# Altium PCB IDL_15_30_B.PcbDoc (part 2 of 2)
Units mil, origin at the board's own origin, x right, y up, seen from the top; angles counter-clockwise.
Board outline 4133.86 x 2440.94 mil, 4 copper layers (Top Layer - SIG1, Layer 2 - GND1, Layer 3 - SIG2, Bottom Layer - SIG4), stack 63.086 mil thick; 140 components, 50 nets, 376 pads, 452 vias.
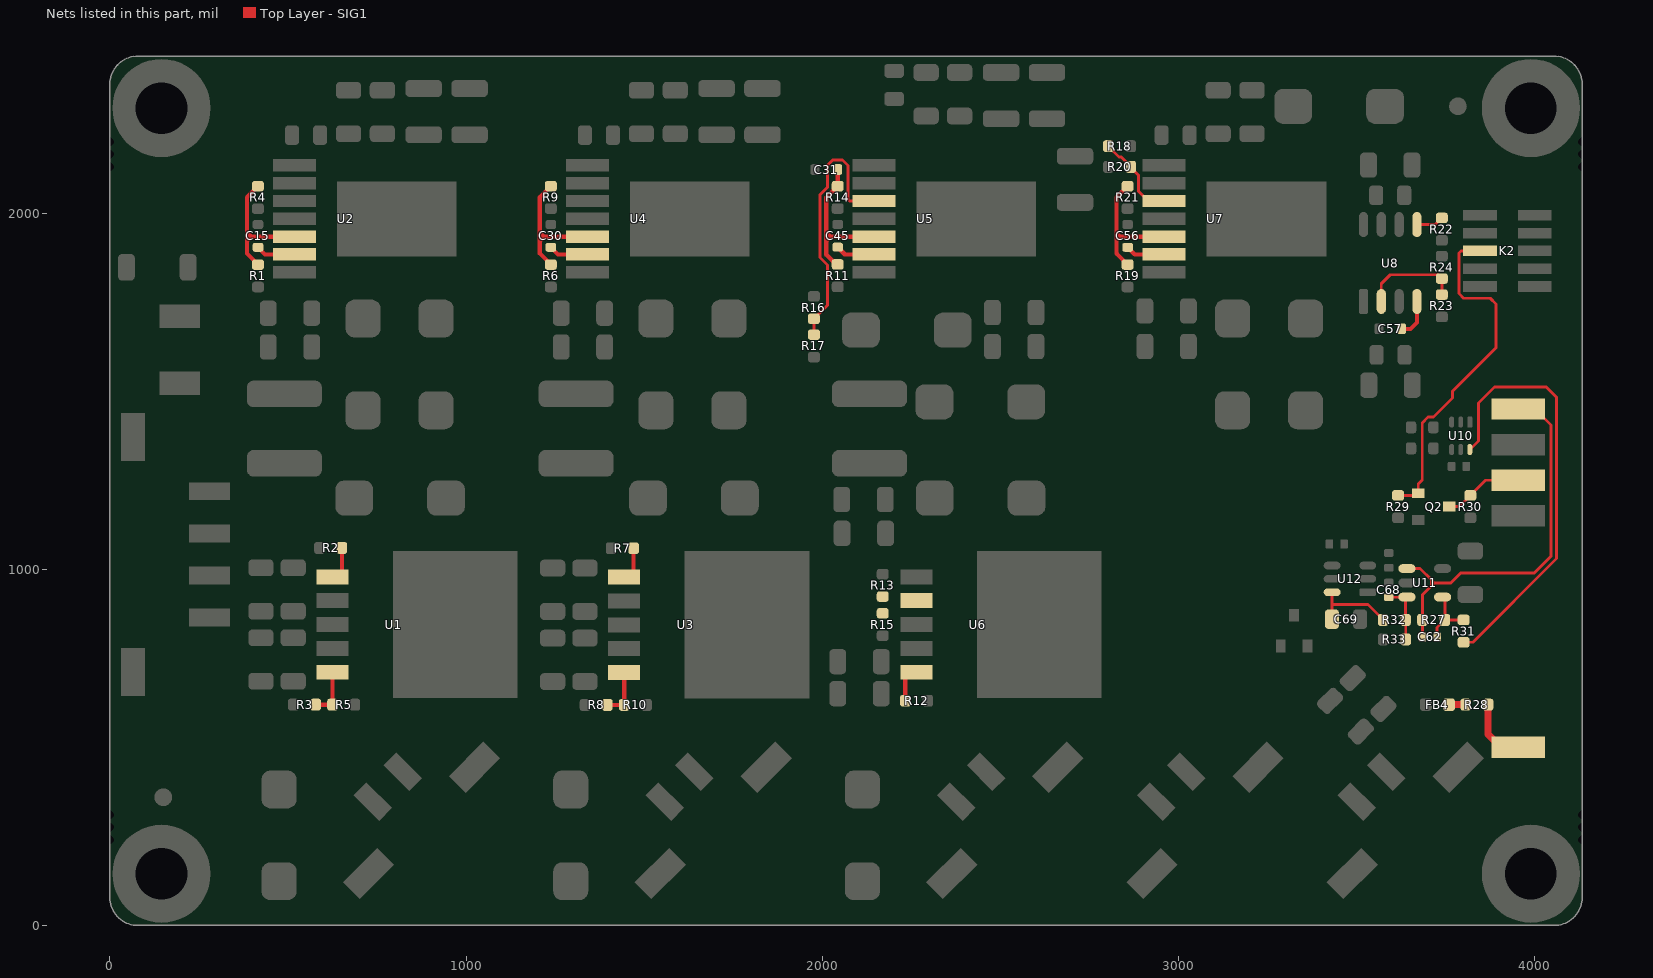
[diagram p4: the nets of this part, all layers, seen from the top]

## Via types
v1: diameter 25.59, hole 11.81, Top Layer - SIG1 to Bottom Layer - SIG4, tented both sides, 262 vias
v2: diameter 31.5, hole 15.75, Top Layer - SIG1 to Bottom Layer - SIG4, tented both sides, 154 vias
v3: diameter 31.5, hole 15.75, Top Layer - SIG1 to Bottom Layer - SIG4, tented top, 36 vias

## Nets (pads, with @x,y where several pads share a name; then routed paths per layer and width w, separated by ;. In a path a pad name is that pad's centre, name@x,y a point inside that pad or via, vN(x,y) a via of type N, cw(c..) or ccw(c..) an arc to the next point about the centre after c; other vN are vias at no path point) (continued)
HVEN#: K2.6 Q2.1 R29.1 | length 981.9
  Top Layer - SIG1 w8: R29.1@3617,1207.5 3667.79,1207.5 Q2.1@3673.69,1213.4 3673.69,1239.69 3684.87,1250.87 3684.87,1411.21 3700.96,1427.29 3716.3,1427.29 3770,1480.99 3770,1499.88 3892,1621.88 3892,1745 3876,1761 3801.05,1761 3787.98,1774.07 3787.98,1887.98 3794,1894 K2.6@3847.23,1894
NetC15_2: C15.2 U2.6 | length 110.7
  Top Layer - SIG1 w12: C15.2@415.87,1904.13 435.87,1884.13 U2.6@518.27,1884.13
NetC30_2: C30.2 U4.6 | length 221.4
  Top Layer - SIG1 w12: 1258.23,1884.13 C30.2@1238.23,1904.13 1258.23,1884.13 ; 1258.23,1884.13 U4.6@1340.63,1884.13 1258.23,1884.13
NetC31_1: C31.1 R11.1 R14.2 U5.5 | length 453.4
  Top Layer - SIG1 w12: 2011.73,1922.27 2023.6,1934.13 ; 2011.73,1946 2023.6,1934.13 ; R11.1@2042.6,1856.99 R11.1@2043.6,1855.99 ; C31.1@2043.6,2122.5 R14.2@2043.6,2075.99 2011.73,2044.13 2011.73,1883.27 2036.57,1858.43 R11.1@2046.03,1858.43 ; U5.5@2145,1934.13 2023.6,1934.13
NetC45_2: C45.2 U5.6 | length 110.7
  Top Layer - SIG1 w12: C45.2@2043.6,1904.5 2063.6,1884.5 ; 2062.6,1884.13 U5.6@2145,1884.13
NetC56_2: C56.2 U7.6 | length 110.7
  Top Layer - SIG1 w12: C56.2@2857.6,1904.13 2877.6,1884.13 U7.6@2960,1884.13
NetC57_1: C57.1 U8.4 | length 109.5
  Top Layer - SIG1 w12: C57.1@3627,1675 3652,1675 3670,1693 U8.4@3670,1752
NetC62_1: C62.1 R27.1 R31.1 U11.4 | length 176.2
  Top Layer - SIG1 w8: C62.1@3726.67,810 3726.67,836.17 R27.1@3748.5,858 ; U11.4@3742,922 3748.5,915.5 R27.1@3748.5,858 ; R31.1@3801,858 R27.1@3748.5,858
NetC62_2: C62.2 pad.1 R27.2 U11.1 | length 1121.2
  Top Layer - SIG1 w8: U11.1@3642,1002 3679,1002 3710,971 ; C62.2@3685.33,810 R27.2@3685.33,857.83 ; R27.2@3685.5,858 3685.5,928.5 3710,953 ; pad.1@3955,1450 pad.1@4001,1450 ; pad.1@4009,1450 pad.1@4001,1450 ; 3710,953 3719,962 ; 3710,953 3710,971 ; 3710,971 3719,962 ; 3719,962 3765,962 3793,990 3999.37,990 4046,1036.63 4046,1405 pad.1@4001,1450
NetC68_2: C68.2 R32.1 R33.2 U11.3 | length 171.2
  Top Layer - SIG1 w8: C68.2@3591,921.33 U11.3@3641.33,921.33 ; R33.2@3638.5,803 3638.5,857.5 R32.1@3638,858 3638,918 U11.3@3641.33,921.33 ; U11.3@3642,922 U11.3@3641.33,921.33
NetC69_2: C69.2 R32.2 U12.6 | length 246.4
  Top Layer - SIG1 w8: C69.2@3431.87,852.13 U12.6@3431.87,935.73 ; 3432,901 3533,901 3576,858 R32.2@3575.01,858
NetFB4_1: FB4.1 R28.2 | length 47
  Top Layer - SIG1 w20: FB4.1@3760,620 R28.2@3807.01,620
NetQ2_3: pad.3 Q2.3 R30.1 | length 233.3
  Top Layer - SIG1 w8: Q2.3@3760.31,1176 3788.5,1176 R30.1@3820,1207.5 3838.5,1226 3862.5,1250 pad.3@3963,1250
NetR1_1: R1.1 R4.2 U2.5 | length 400.5
  Top Layer - SIG1 w12: R1.1@415.87,1855.63 385,1886.5 385,1922.27 ; R4.2@415.87,2075.63 387.13,2046.9 385,2044.76 385,1946 ; U2.5@518.27,1934.13 396.87,1934.13 ; 385,1922.27 385,1946 ; 385,1922.27 396.87,1934.13 ; 385,1946 396.87,1934.13
NetR2_1: R2.1 U1.1 | length 100.2
  Top Layer - SIG1 w12: U1.1@625,979 639,979 651.5,991.5 R2.1@651.5,1060
NetR3_1: R3.1 R5.2 U1.5 | length 138
  Top Layer - SIG1 w12: R3.1@577.99,620 R5.2@625,620 U1.5@625,711
NetR6_1: R6.1 R9.2 U4.5 | length 400.5
  Top Layer - SIG1 w12: R6.1@1238.23,1855.63 1207.36,1886.5 1207.36,1922.27 ; R9.2@1238.23,2075.63 1209.5,2046.9 1207.36,2044.76 1207.36,1946 ; U4.5@1340.63,1934.13 1219.23,1934.13 ; 1207.36,1922.27 1219.23,1934.13 ; 1207.36,1922.27 1207.36,1946 ; 1207.36,1946 1219.23,1934.13
NetR7_1: R7.1 U3.1 | length 100.2
  Top Layer - SIG1 w12: U3.1@1444.05,978.13 1458.05,978.13 1470.55,990.63 R7.1@1470.55,1059.13
NetR8_1: R8.1 R10.2 U3.5 | length 138
  Top Layer - SIG1 w12: R8.1@1397.05,619.13 R10.2@1444.05,619.13 U3.5@1444.05,710.13
NetR12_1: R12.1 U6.5 | length 80
  Top Layer - SIG1 w12: R12.1@2233.5,631 U6.5@2233.5,711
NetR13_1: R13.1 R15.2 U6.2
NetR16_2: R16.2 R17.1 U5.3 | length 749
  Top Layer - SIG1 w8: R17.1@1977,1659 R16.2@1977,1703.5 2014.87,1741.37 2014.87,1854.68 1993.73,1875.81 1993.73,2051.58 2014.87,2072.72 2014.87,2134.57 2029.79,2149.5 2057.41,2149.5 2072.76,2134.14 2072.76,2038.24 2076.87,2034.13 U5.3@2145,2034.13
NetR18_1: R18.1 R20.1 U7.3 | length 249
  Top Layer - SIG1 w8: R18.1@2803.5,2188 2803.5,2187.5 2833,2158 2840,2158 2866.5,2131.5 R20.1@2866.5,2130 2866.5,2127.64 2887.76,2106.37 2887.76,2061.64 2915.27,2034.13 U7.3@2960,2034.13
NetR19_1: R19.1 R21.2 U7.5 | length 396.9
  Top Layer - SIG1 w12: 2826.73,1924.27 2836.6,1934.13 ; 2826.73,1944 2836.6,1934.13 ; R19.1@2857.6,1855.63 2828.87,1884.36 2826.73,1886.5 2826.73,2044.76 R21.2@2857.6,2075.63 ; U7.5@2960,1934.13 2836.6,1934.13
NetR22_1: R22.1 U8.5 | length 77.7
  Top Layer - SIG1 w8: U8.5@3670,1968 3721.5,1968 R22.1@3740,1986.5
NetR23_1: R23.1 R24.2 U8.2 | length 279.6
  Top Layer - SIG1 w8: U8.2@3570,1752 3570,1802 3595,1827 3729.38,1827 R24.2@3740,1816.38 R23.1@3740,1771.5
NetR28_1: pad.5 R28.1 | length 208.9
  Top Layer - SIG1 w20: R28.1@3870,620 3870,536 3906,500 pad.5@3980,500
NetR31_2: R31.2 U10.6 | length 1201.9
  Top Layer - SIG1 w8: R31.2@3801,795.01 3827.01,795.01 4062,1030 4062,1483 4033,1512 3888,1512 3843,1467 3843,1360.64 U10.6@3818.59,1336.23
pads on no net: FID1.0 FID2.0 K1.MP1 K1.MP2 K4.MP1 K4.MP2 K5.MP1 K5.MP2 K6.MP1 K6.MP2 K7.MP1 K7.MP2 K8.MP1 K8.MP2 ME1.0 ME1.1 ME1.2 ME2.0 ME2.1 ME2.2 ME3.0 ME3.1 ME3.2 ME4.0 ME4.1 ME4.2

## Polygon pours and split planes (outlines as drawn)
+12VIN_3 on Top Layer - SIG1 "L1_+12V" (solid, remove dead copper, pour order 0): 20,1580 355,1580 355,2057 376,2078 376,2095 391,2110 616,2110 616,2134 570,2180 570,2242 576,2248 1052,2248 1062,2238 1062,2130 1085,2107 1438,2107 1438.36,2107.36 1438.36,2134 1392.36,2180 1392.36,2242 1398.36,2248 1874.36,2248 1884.36,2238 1884.36,2173.64 1905,2153 2053.9,2153 2072.76,2134.14 2072.76,2110 2757.76,2110 2769,2121.24 2769,2160 2769,2200 2777,2208 2816,2208 2821,2203 2821,2170 2833,2158 2840,2158 2866.5,2131.5 2887.76,2110.24 2887.76,2106.37 3057.37,2106.37 3058,2107 3057.73,2134 3011.73,2180 3011.73,2242 3017.73,2248 3237.16,2248 3407.39,2077.77 3458,2077.77 3458,1932 3470,1920 3531,1920 3543,1932 3543,1998 3555,2010 3577,2010 3589,2022 3589,2139 3522,2206 3307,2421 3191,2421 295,2421 295,2232 208,2145 20,2145
GND on Top Layer - SIG1 "L1_GND" (solid, remove dead copper, pour order 4): 20,2157 20,2363 cw(c78,2363) 78,2421 4054,2421 cw(c4054,2361) 4114,2361 4114,80 cw(c4054,80) 4054,20 75.15,20 cw(c75.15,75.15) 20,75.15
GND on Layer 3 - SIG2 "L3_GND" (solid, remove dead copper, pour order 6): 20,2157 20,2363 cw(c78,2363) 78,2421 4054,2421 cw(c4054,2361) 4114,2361 4114,80 cw(c4054,80) 4054,20 75.15,20 cw(c75.15,75.15) 20,75.15
GND on Bottom Layer - SIG4 "L4_GND" (solid, remove dead copper, pour order 8): 20,2157 20,2363 cw(c78,2363) 78,2421 4054,2421 cw(c4054,2361) 4114,2361 4114,80 cw(c4054,80) 4054,20 75.15,20 cw(c75.15,75.15) 20,75.15
GND on Layer 2 - GND1 (split plane): 4061.69,2420.57 4068.19,2419.46 4074.52,2417.64 4080.6,2415.12 4086.37,2411.94 4091.74,2408.12 4096.65,2403.73 4101.04,2398.82 4104.85,2393.45 4108.03,2387.69 4110.55,2381.6 4112.38,2375.27 4113.48,2368.78 4113.82,2362.78 4113.76,2362.2 4113.76,78.74 4113.82,78.16 4113.48,72.16 4112.38,65.67 4110.55,59.34 4108.03,53.26 4104.85,47.49 4101.04,42.12 4096.65,37.21 4091.74,32.82 4086.37,29.01 4080.6,25.82 4074.52,23.3 4068.19,21.48 4061.69,20.38 4055.69,20.04 4055.12,20.1 78.74,20.1 78.16,20.04 72.16,20.38 65.67,21.48 59.34,23.3 53.26,25.82 47.49,29.01 42.12,32.82 37.21,37.21 32.82,42.12 29.01,47.49 25.82,53.26 23.3,59.34 21.48,65.67 20.38,72.16 20.04,78.16 20.1,78.74 20.1,2362.2 20.04,2362.78 20.38,2368.78 21.48,2375.27 23.3,2381.6 25.82,2387.69 29.01,2393.45 32.82,2398.82 37.21,2403.73 42.12,2408.12 47.49,2411.94 53.26,2415.12 59.34,2417.64 65.67,2419.46 72.16,2420.57 78.16,2420.9 78.74,2420.85 4055.12,2420.85 4055.69,2420.9

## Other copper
Top Layer - SIG1:
  pour cut-out: 2200,1858.61 2252.68,1858.61 2252.68,1957.84 2200,1957.84
  pour cut-out: 1178.65,1297.65 1189.9,1297.65 1189.9,1289 1182.24,1289
  pour cut-out: 1192.29,297.37 1182.24,297.37 1182.24,303.13 1198.05,303.13
  region net +5VA_SW1_3: 1278.36,1858 1406.36,1858 1413.36,1851 1413.36,1804 1402.36,1793 1360.36,1793 1332.36,1765 1332.36,1588 1358.36,1562 1884.36,1562 1884.36,1418 1842.36,1376 1238.36,1376 1201.36,1413 1201.36,1803 1214.36,1816 1245.36,1816 1264.39,1835.03 1264.39,1844.03
  region net +3VA_SW2_3: 379,1328 379,939 394,924 538,924 574,888 672,888 672,945 577,945 568,954 568,1006 577,1015 610,1015 622,1027 622,1075 637,1090 741,1090 760,1109 760,1331 741,1350 401,1350
  region net +3VA_SW1_3: 456,1858 584,1858 591,1851 591,1804 580,1793 538,1793 510,1765 510,1588 536,1562 1062,1562 1062,1418 1020,1376 416,1376 379,1413 379,1803 392,1816 423,1816 442.03,1835.03 442.03,1844.03
  region net GND: 1221.36,2023 1227.36,2029 1251.36,2029 1277.36,2003 1498.11,2003 1498.11,1966 1262.36,1966 1250.36,1954 1227.36,1954 1221.36,1960
  region net GND: 399,2023 405,2029 429,2029 455,2003 675.75,2003 675.75,1966 440,1966 428,1954 405,1954 399,1960
  region net GND: 1392.36,2242 1398.36,2248 1874.36,2248 1884.36,2238 1884.36,1586 1368.36,1586 1356.36,1598 1356.36,1755 1370.36,1769 1412.36,1769 1438.36,1795 1438.36,2134 1392.36,2180
  region net GND: 570,2242 576,2248 1052,2248 1062,2238 1062,1586 546,1586 534,1598 534,1755 548,1769 590,1769 616,1795 616,2134 570,2180
  region net GND: 20,1046.85 335,1046.85 350,1031.85 350,806.85 335,791.85 20,791.85
  region net +12VIN*_3: 335,1056.85 353,1074.85 353,1566.85 348,1571.85 20,1571.85 20,1451.85 100,1451.85 110,1441.85 110,1071.85 125,1056.85
  region net GND: 3453,1040 3453,1082 3458,1087 3499,1087 3565,1021 3602,1021 3609,1014 3609,988 3618,979 3663,979 3669,973 3669,951 3663,945 3575,945 3554,924 3499,924 3483,940 3483,1010
  region net GND: 3795,885 3875,885 3895,905 3895,945 3875,965 3795,965 3780,950 3780,900
  region net GND: 3464,881 3472,889 3527,889 3545,871 3545,846 3561,830 3586,830 3594,822 3594,774 3587,767 3557,767 3496,828 3472,828 3464,836
  region net GND: 2145,2421 2715,2421 2715,2380 2705,2370 2154,2370 2145,2379
  region net GND: 378.9,892.9 394,908 541,908 580,869 970,869 970,820 580,820 541,781 393.9,781 378.9,796
  region net +2V5_3: 379,743 407,771 543,771 582,810 672,810 672,751 587,751 564,728 564,649 554,639 554,599 813,340 813,314 750,251 432,251 379,304
  region net GND: 1197.95,892.03 1213.05,907.13 1360.05,907.13 1399.05,868.13 1789.05,868.13 1789.05,819.13 1399.05,819.13 1360.05,780.13 1212.95,780.13 1197.95,795.13
  region net +4V5A_3: 1198.05,742.13 1226.05,770.13 1362.05,770.13 1401.05,809.13 1491.05,809.13 1491.05,750.13 1406.05,750.13 1383.05,727.13 1383.05,648.13 1373.05,638.13 1373.05,598.13 1632.05,339.13 1632.05,313.13 1569.05,250.13 1251.05,250.13 1198.05,303.13
  region net -5.4VA_SW1_3: 2025.73,2023 2031.73,2029 2055.73,2029 2081.73,2003 2432.6,2003 2432.6,1966 2066.73,1966 2054.73,1954 2031.73,1954 2025.73,1960
  region net +5VA_SW2_3: 1198.05,1328 1198.05,939 1213.05,924 1357.05,924 1393.05,888 1491.05,888 1491.05,945 1396.05,945 1387.05,954 1387.05,1006 1396.05,1015 1429.05,1015 1441.05,1027 1441.05,1075 1456.05,1090 1560.05,1090 1579.05,1109 1579.05,1331 1560.05,1350 1220.05,1350
  region net -5.4VA_SW1_3: 2252,2097.04 2265.08,2110.12 2757.88,2110.12 2769,2099 2769,2004 2530,1765 2530,1597 2353,1420 2049.77,1420 2016.77,1453 2016.77,1493 1960,1549.77 1960,1608 1965,1613 1998,1613 2042,1569 2176,1569 2252,1645
  region net GND: 2027,1809 2036,1818 2057,1818 2068,1829 2068,1843 2080,1855 2234,1855 2243,1846 2243,1650 2172,1579 2046,1579 2008,1617 2008,1717 2027,1736
  region net -5.4VA_SW2_3: 2016,1322 2045,1351 2270,1351 2582,1039 2582,638 2431,638 2331,738 2331,997 2318,1010 2151,1010 2115,1046 2115,1231 2100,1246 2026,1246 2016,1256
  region net NetR13_1: 2154,861 2150,865 2150,932 2159,941 2315,941 2315,887 2212,887 2186,861
  region net -4V5A_3: 2103,772 2103,814 2120.09,831.09 2198.09,831.09 2220.05,809.13 2310.05,809.13 2310.05,750.13 2225.05,750.13 2209,734.08 2209,581.19 2451.05,339.13 2451.05,313.13 2388.05,250.13 2070.05,250.13 2017.05,303.13 2017.06,423.13 2017.06,526.06 2103,612
  region net GND: 3011.73,2242 3017.73,2248 3237.16,2248 3458,2077.77 3458,1586 2987.73,1586 2975.73,1598 2975.73,1755 2989.73,1769 3031.73,1769 3057.73,1795 3057.73,2134 3011.73,2180
  region net +3V3D_3: 2897.73,1858 3025.73,1858 3032.73,1851 3032.73,1804 3021.73,1793 2979.73,1793 2951.73,1765 2951.73,1588 2977.73,1562 3458,1562 3458,1395.27 3438.73,1376 3007,1376 2977.73,1346.73 2977.73,518 2937.86,478.14 2937.86,458 2988.43,407.43 3040.43,355.43 3040.43,305 3015.22,279.78 2867.95,279.78 2820.73,327 2820.73,518 2820.73,1413 2820.73,1803 2833.73,1816 2864.73,1816 2883.76,1835.03 2883.76,1844.03
  region net +5HV: 3700,1121 3700,1280 3740,1320 3740,1347 3746,1353 3774,1353 3778,1349 3778,1238 3734,1194 3734,1159 3742,1151 3786,1151 3819,1184 4032,1184 4032,1045 3992,1005 3790,1005 3760,975 3730,975 3676,1029 3569,1029 3503,1095 3454,1095 3445,1086 3445,1036 3464,1017 3464,1001 3457,994 3411,994 3403,1002 3403,1327 3468,1392 3468,1793 3536,1793 3543,1786 3543,1724 3591,1676 3591,1500 3671,1420 3671,1376 3662,1367 3641,1367 3630,1356 3630,1260 3592,1222 3592,1175 3600,1167 3634,1167 3642,1159 3642,1124 3651,1115 3694,1115
  region net GND: 20,1901.85 83,1901.85 99,1885.85 99,1809.85 83,1793.85 20,1793.85
  region net GND: 2840.73,2023 2846.73,2029 2870.73,2029 2896.73,2003 3117.48,2003 3117.48,1966 2881.73,1966 2869.73,1954 2846.73,1954 2840.73,1960
  pour cut-out: 1072.2,2119.8 1072.2,1562 536,1562 510,1588 510,1765 538,1793 580,1793 580,1916 561,1935 396,1935 385,1946 385,2044.76 451,2102 755,2102 1057.87,2134.13
  pour cut-out: 1894.56,2163.44 1894.56,1562 1358.36,1562 1332.36,1588 1332.36,1765 1360.36,1793 1402.36,1793 1402.36,1916 1383.36,1935 1218.36,1935 1207.36,1946 1207.36,2044.76 1273.36,2102 1577.36,2102 1873,2163.44
  pour cut-out: 3468.2,1921.8 3468.2,1562 2977.73,1562 2951.73,1588 2951.73,1765 2979.73,1793 3021.73,1793 3021.73,1916 3002.73,1935 2837.73,1935 2826.73,1946 2826.73,2044.76 2892.73,2102 3196.73,2102
  pour cut-out: 371.46,935.88 370.84,939 370.84,740 394,740 407,771 407,911 394,924
  pour cut-out: 1154.05,848.94 1187.86,815.13 1187.86,739.13 1213.05,739.13 1226.05,770.13 1226.05,910.13 1213.05,923.13
  pour cut-out: 379,304 379,11 368.8,11 368.8,309.45

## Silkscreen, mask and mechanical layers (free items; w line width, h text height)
Top Overlay:
  lines w3.94: 3500,1350 3500,1110 3570,1050 3570,920
  text "+12V" at 215,2025 h120 r45
  text "UHM-HEP Group" at 2931.94,551.35 h59.06 r90
  text "ID Laboratory" at 3016.94,551.35 h59.06 r90
  text "IDL_15_30 Rev.B" at 3101.94,551.35 h47.24 r90
  text "HV" at 3739.43,107.43 h120 r45
  text "+2V5" at 935,65 h120 r45
  text "+4V5A" at 1754,65 h120 r45
  text "-4V5A" at 2573,65 h120 r45
  text "+3V3D" at 3135,65 h120 r45
Bottom Solder:
  region: 78.74,0 cw(c78.74,78.74) 0,78.74 0,2362.2 cw(c78.74,2362.2) 78.74,2440.94 4055.12,2440.94 cw(c4055.12,2362.2) 4133.86,2362.2 4133.86,78.74 cw(c4055.12,78.74) 4055.12,0
Board Outline:
  the board outline again, w3.94
Sheet Top:
  lines w3.9: -1853.54,-7404.63 -1853.54,4075.28 13946.37,4075.28 13946.37,-7404.63 -1853.54,-7404.63 ; -1753.28,-7304.92 -1753.28,3975.57 13846.1,3975.57 13846.1,-7304.92 -1753.28,-7304.92
  lines w3.94: 7156.46,-7304.92 7156.46,-6594.72 13846.1,-6594.72 ; 7156.46,-6953.96 13846.46,-6953.96 ; 7156.46,-6834.72 11976.46,-6834.72 ; 7156.46,-6714.72 11976.46,-6714.72 ; 8661.46,-6953.96 8661.46,-6594.72 ; 9661.46,-6953.96 9661.46,-6594.72 ; 11251.46,-6953.96 11251.46,-6594.72 ; 11976.46,-7304.92 11976.46,-6594.72 ; 11976.46,-6774.72 13846.1,-6774.72
  text "Designer:" at 7181.46,-6684.72 h100
  text ".Designer" at 7746.46,-6689.72 h100
  text "Revision:" at 8686.46,-6689.72 h100
  text ".Version" at 9246.46,-6689.72 h100
  text "File:" at 9686.46,-6689.72 h100
  text ".Pcb_File_Name_No_Path" at 9886.46,-6689.72 h100
  text "Sheet  1 of  1" at 11281.46,-6689.72 h100
  text "Code:" at 12001.46,-6734.72 h100
  text "Drawn By:" at 7181.46,-6804.72 h100
  text ".Drawn_By" at 7746.46,-6804.72 h100
  text "Modif. Date:" at 8686.46,-6809.72 h100
  text "Date" at 9191.46,-6809.72 h100
  text "Variant:" at 9686.46,-6809.72 h100
  text ".VariantName" at 10051.46,-6809.72 h100
  text "ID:" at 12006.46,-6914.72 h100
  text "Approved By:" at 7181.46,-6924.72 h100
  text ".Approved_By" at 7746.46,-6924.72 h100
  text "Print Date:" at 8686.46,-6929.72 h100
  text ".Print_Date" at 9191.46,-6929.72 h100
  text "Signature:" at 9686.46,-6929.72 h100
  text "Size:  A3 H" at 11281.46,-6929.72 h100
  text "Title:" at 7181.46,-7054.72 h100
  text "University of Hawaii at Manoa" at 12007.87,-7062.99 h100
  text "High Energy Physics Group" at 12007.87,-7161.42 h100
  text ".Printout_Name" at 7406.46,-7194.72 h160
  text "Instrumentation Development Laboratory" at 12007.87,-7263.78 h100
Sheet Bot:
  lines w3.9: -1853.81,-7404.43 13946.1,-7404.43 13946.1,4075.47 -1853.81,4075.47 -1853.81,-7404.43 ; -1753.54,-7304.72 13845.84,-7304.72 13845.84,3975.77 -1753.54,3975.77 -1753.54,-7304.72
  lines w3.94: -1753.9,-6953.77 4936.1,-6953.77 ; -1753.54,-6774.53 116.1,-6774.53 ; -1753.54,-6594.53 4936.1,-6594.53 4936.1,-7304.72 ; 116.1,-7304.72 116.1,-6594.53 ; 116.1,-6834.53 4936.1,-6834.53 ; 116.1,-6714.53 4936.1,-6714.53 ; 841.1,-6953.77 841.1,-6594.53 ; 2431.1,-6953.77 2431.1,-6594.53 ; 3431.1,-6953.77 3431.1,-6594.53
  text "Designer:" at 4911.1,-6684.53 h100
  text "Sheet  1 of  1" at 811.1,-6689.53 h100
  text ".Pcb_File_Name_No_Path" at 2206.1,-6689.53 h100
  text "File:" at 2406.1,-6689.53 h100
  text ".Version" at 2846.1,-6689.53 h100
  text "Revision:" at 3406.1,-6689.53 h100
  text ".Designer" at 4346.1,-6689.53 h100
  text "Code:" at 91.1,-6734.53 h100
  text ".Drawn_By" at 4346.1,-6804.53 h100
  text "Drawn By:" at 4911.1,-6804.53 h100
  text ".VariantName" at 2041.1,-6809.53 h100
  text "Variant:" at 2406.1,-6809.53 h100
  text "Date" at 2901.1,-6809.53 h100
  text "Modif. Date:" at 3406.1,-6809.53 h100
  text "ID:" at 86.1,-6914.53 h100
  text ".Approved_By" at 4346.1,-6924.53 h100
  text "Approved By:" at 4911.1,-6924.53 h100
  text "Size:  A3 H" at 811.1,-6929.53 h100
  text "Signature:" at 2406.1,-6929.53 h100
  text ".Print_Date" at 2901.1,-6929.53 h100
  text "Print Date:" at 3406.1,-6929.53 h100
  text "Title:" at 4911.1,-7054.53 h100
  text "University of Hawaii at Manoa" at 82.75,-7066.93 h100
  text "High Energy Physics Group" at 82.75,-7165.36 h100
  text ".Printout_Name" at 4686.1,-7194.53 h160
  text "Instrumentation Development Laboratory" at 82.75,-7267.72 h100
FabNTop:
  text ".IDLnum" at 12301.46,-6734.72 h160
  text "ASSEMBLY" at 11281.49,-6811.02 h100
  text ".BoardName" at 12301.46,-6914.72 h160
FabNBot:
  text ".IDLnum" at -208.9,-6734.53 h160
  text "ASSEMBLY" at 811.02,-6811.02 h100
  text ".BoardName" at -208.9,-6914.53 h160
PCBNTop:
  text ".IDLnum" at 12301.46,-6734.72 h160
  text "PCB" at 11281.49,-6811.02 h100
  text ".BoardName" at 12301.46,-6914.72 h160
PCBNBot:
  text ".IDLnum" at -208.66,-6734.25 h160
  text "PCB" at 811.02,-6811.02 h100
  text ".BoardName" at -208.9,-6914.53 h160
MechTop:
  circle w4: c145,2295 r72.5
  circle w4: c145,145 r72.5
  circle w4: c3990,145 r72.5
  circle w4: c3990,2295 r72.5
  text "Mounting Hole Size: 145mil" at 1190,-235 h60
Mech 11:
  lines w3.94: 2265.08,1858.15 2265.08,2110.12 2432.6,2110.12 2605.04,2110.12 2605.04,1858.15 2265.08,1858.15
Mech 12:
  region: -797.34,2918.79 -787.22,2918.79 cw(c-787.22,2860) -728.43,2860 cw(c-786.6,2860) -786.6,2801.84 -797.34,2801.84
  region: -797.43,2447.53 -787.32,2447.53 cw(c-787.32,2388.74) -728.53,2388.74 cw(c-786.69,2388.74) -786.69,2330.58 -797.43,2330.58
  region: -797.43,1976.27 -787.32,1976.27 cw(c-787.32,1917.48) -728.53,1917.48 cw(c-786.69,1917.48) -786.69,1859.32 -797.43,1859.32
  region: -797.43,1505.01 -787.32,1505.01 cw(c-787.32,1446.22) -728.53,1446.22 cw(c-786.69,1446.22) -786.69,1388.06 -797.43,1388.06
  region: -797.43,1033.75 -787.32,1033.75 cw(c-787.32,974.96) -728.53,974.96 cw(c-786.69,974.96) -786.69,916.8 -797.43,916.8
  region: -797.43,562.49 -787.32,562.49 cw(c-787.32,503.7) -728.53,503.7 cw(c-786.69,503.7) -786.69,445.54 -797.43,445.54
  region: -797.43,91.23 -787.32,91.23 cw(c-787.32,32.44) -728.53,32.44 cw(c-786.69,32.44) -786.69,-25.72 -797.43,-25.72
  region: -797.43,-380.03 -787.32,-380.03 cw(c-787.32,-438.82) -728.53,-438.82 cw(c-786.69,-438.82) -786.69,-496.98 -797.43,-496.98
  region: 5116.56,-281.21 5106.45,-281.21 ccw(c5106.45,-340) 5047.66,-340 ccw(c5105.82,-340) 5105.82,-398.16 5116.56,-398.16
  region: 5116.56,190.69 5106.45,190.69 ccw(c5106.45,131.9) 5047.66,131.9 ccw(c5105.82,131.9) 5105.82,73.74 5116.56,73.74
  region: 5116.56,661.95 5106.45,661.95 ccw(c5106.45,603.16) 5047.66,603.16 ccw(c5105.82,603.16) 5105.82,545 5116.56,545
  region: 5116.56,1133.21 5106.45,1133.21 ccw(c5106.45,1074.42) 5047.66,1074.42 ccw(c5105.82,1074.42) 5105.82,1016.25 5116.56,1016.25
  region: 5116.56,1604.47 5106.45,1604.47 ccw(c5106.45,1545.68) 5047.66,1545.68 ccw(c5105.82,1545.68) 5105.82,1487.51 5116.56,1487.51
  region: 5116.56,2075.73 5106.45,2075.73 ccw(c5106.45,2016.94) 5047.66,2016.94 ccw(c5105.82,2016.94) 5105.82,1958.77 5116.56,1958.77
  region: 5116.56,2546.99 5106.45,2546.99 ccw(c5106.45,2488.2) 5047.66,2488.2 ccw(c5105.82,2488.2) 5105.82,2430.03 5116.56,2430.03
  region: 5116.56,3018.25 5106.45,3018.25 ccw(c5106.45,2959.46) 5047.66,2959.46 ccw(c5105.82,2959.46) 5105.82,2901.29 5116.56,2901.29
  lines w3.94: -797.43,2918.79 -797.34,2918.79 ; -961.43,-1070 5308.56,-1070 5308.56,3650 -961.43,3650 -961.43,-1070
  lines w10: -797.43,-496.98 -797.43,-380.03 cw(c-788.33,-438.5) -797.34,-496.98 ; -797.43,-25.72 -797.43,91.23 cw(c-788.33,32.76) -797.34,-25.72 ; -797.43,445.54 -797.43,562.49 cw(c-788.33,504.02) -797.34,445.54 ; -797.43,916.8 -797.43,1033.75 cw(c-788.33,975.28) -797.34,916.8 ; -797.43,1388.06 -797.43,1505.01 cw(c-788.33,1446.54) -797.34,1388.06 ; -797.43,1859.32 -797.43,1976.27 cw(c-788.33,1917.8) -797.34,1859.32 ; -797.43,2330.58 -797.43,2447.53 cw(c-788.33,2389.06) -797.34,2330.58 ; -797.43,2918.79 cw(c-788.33,2860.32) -797.34,2801.84 -797.34,2918.79 ; 5116.47,-398.16 cw(c5107.46,-339.68) 5116.56,-281.21 5116.56,-398.16 ; 5116.47,73.74 cw(c5107.46,132.22) 5116.56,190.69 5116.56,73.74 ; 5116.47,545 cw(c5107.46,603.48) 5116.56,661.95 5116.56,545 ; 5116.47,1016.25 cw(c5107.46,1074.74) 5116.56,1133.21 5116.56,1016.25 ; 5116.47,1487.51 cw(c5107.46,1546) 5116.56,1604.47 5116.56,1487.51 ; 5116.47,1958.77 cw(c5107.46,2017.26) 5116.56,2075.73 5116.56,1958.77 ; 5116.47,2430.03 cw(c5107.46,2488.52) 5116.56,2546.99 5116.56,2430.03 ; 5116.47,2901.29 cw(c5107.46,2959.78) 5116.56,3018.25 5116.56,2901.29
Drill Drawing:
  drawing of 222 lines, arcs and shapes, not listed
  text "Table 1a: Layer Stack Details for IDL_15_30 Rev.B (Metric Units)" at 7933.07,-1862.21 h98.43
  text "Layer" at 8004.51,-2099.19 h60
  text "Name" at 8255.6,-2099.19 h60
  text "Material" at 8858.45,-2099.19 h60
  text "Thickness" at 9294.8,-2099.19 h60
  text "Constant" at 9653.23,-2099.19 h60
  text "Board Layer Stack" at 9984.96,-2099.19 h60
  text "1" at 8004.51,-2219.19 h60
  text "Top Overlay" at 8255.6,-2219.19 h60
  text "2" at 8004.51,-2339.19 h60
  text "Top Solder" at 8255.6,-2339.19 h60
  text "Solder Resist" at 8858.45,-2339.19 h60
  text "0,010mm" at 9294.8,-2339.19 h60
  text "3,5" at 9653.23,-2339.19 h60
  text "3" at 8004.51,-2459.19 h60
  text "Top Layer - SIG1" at 8255.6,-2459.19 h60
  text "Copper" at 8858.45,-2459.19 h60
  text "0,055mm" at 9294.8,-2459.19 h60
  text "4" at 8004.51,-2579.19 h60
  text "Dielectric 1" at 8255.6,-2579.19 h60
  text "FR-4" at 8858.45,-2579.19 h60
  text "0,381mm" at 9294.8,-2579.19 h60
  text "4,65" at 9653.23,-2579.19 h60
  text "Notes:" at -1376.47,-2602.93 h130
  text "5" at 8004.51,-2699.19 h60
  text "Layer 2 - GND1" at 8255.6,-2699.19 h60
  text "Copper" at 8858.45,-2699.19 h60
  text "0,035mm" at 9294.8,-2699.19 h60
  text "1. Board shall be fabricated - performace class II as per IPC-6011 and IPC6012" at -1376.47,-2727.93 h100
  text "6" at 8004.51,-2819.19 h60
  text "Dielectric 3" at 8255.6,-2819.19 h60
  text "FR-4" at 8858.45,-2819.19 h60
  text "0,660mm" at 9294.8,-2819.19 h60
  text "4,65" at 9653.23,-2819.19 h60
  text "2. PCB manufacturer logo, P/N, revision and/or date code of manufacturing" at -1376.47,-2852.93 h100
  text "7" at 8004.51,-2939.19 h60
  text "Layer 3 - SIG2" at 8255.6,-2939.19 h60
  text "Copper" at 8858.45,-2939.19 h60
  text "0,035mm" at 9294.8,-2939.19 h60
  text "shall be printed in top solder mask (not over pcb traces, allowed over copper plane)." at -1276.47,-2952.93 h100
  text "The date code shall be in the format: \"WWYY\" where WW=week and YY= year, max height 0.15 inches" at -1276.47,-3052.93 h100
  text "8" at 8004.51,-3059.19 h60
  text "Dielectric 6" at 8255.6,-3059.19 h60
  text "FR-4" at 8858.45,-3059.19 h60
  text "0,381mm" at 9294.8,-3059.19 h60
  text "4,65" at 9653.23,-3059.19 h60
  text "3. Silkscreen printed on top side" at -1376.47,-3177.93 h100
  text "9" at 8004.51,-3179.19 h60
  text "Bottom Layer - SIG4" at 8255.6,-3179.19 h60
  text "Copper" at 8858.45,-3179.19 h60
  text "0,055mm" at 9294.8,-3179.19 h60
  text "10" at 8004.51,-3299.19 h60
  text "Bottom Solder" at 8255.6,-3299.19 h60
  text "Solder Resist" at 8858.45,-3299.19 h60
  text "0,010mm" at 9294.8,-3299.19 h60
  text "3,5" at 9653.23,-3299.19 h60
  text "4. Material: high temperature FR4 class epoxy glass rated UL94V-0. UL symbol and rating shall be marked farside" at -1376.47,-3302.93 h100
  text "55um copper for external layers and 35um for all internal layers" at -1276.46,-3402.93 h100
  text "11" at 8004.51,-3419.19 h60
  text "Bottom Overlay" at 8255.6,-3419.19 h60
  text "Must be RoHS compliant and survive a lead-free assembly max reflow of 260 deg C (5 passes)" at -1276.47,-3502.93 h100
  text "Td rating: >340 deg C" at -1226.47,-3627.93 h100
  text "Tg = 150 deg C (min)" at -1222.44,-3738.19 h100
  text "5. Solder mask: SMOBC per IPC-SM-840C, class T must be Rohs compliant, 0.001\" max measured over bare copper plating," at -1376.47,-3977.93 h100
  text "must clear all lands as indicated on gerber solder mask layers, color= GREEN" at -1276.47,-4077.93 h100
  text "6. Finish: HAL-Sn100CL,  7-10 um - over bare copper only" at -1376.69,-4231.75 h100
  text "Table 2: NC Drill Details for IDL_15_30 Rev.B" at 7933.07,-4303.15 h98.43
  text "7. Solderability test: Category 2 of J-STD-003" at -1376.47,-4377.93 h100
  text "8. Finished boards shall not have nicks, scratches, voids, exposed copper, poor plating or misdrilled holes" at -1376.47,-4527.93 h100
  text "Symbol" at 8034.51,-4599.07 h72
  text "Hit Count" at 8540.38,-4599.07 h72
  text "Finished Hole Size" at 9238.2,-4599.07 h72
  text "Plated" at 10583.8,-4599.07 h72
  text "Hole Type" at 11089.68,-4599.07 h72
  text "9. All holes sizes are after plating" at -1376.47,-4677.93 h100
  text "4" at 8540.38,-4749.07 h60
  text "3,683mm (145,00mil)" at 9238.2,-4749.07 h60
  text "PTH" at 10583.8,-4749.07 h60
  text "Round" at 11089.68,-4749.07 h60
  text "10. PCB manufacturer may add copper thieving as needed to improve manufacturability," at -1426.47,-4827.93 h100
  text "24" at 8540.38,-4899.07 h60
  text "0,600mm (23,62mil)" at 9238.2,-4899.07 h60
  text "NPTH" at 10583.8,-4899.07 h60
  text "Round" at 11089.68,-4899.07 h60
  text "thieving to be 0.030\" round pads at 0.050\" spacing." at -1276.47,-4927.93 h100
  text "Thieving will have a minimum of 0.100\" clearance from existing copper and should not be placed under surface mounted devices" at -1276.47,-5027.93 h100
  text "190" at 8540.38,-5049.07 h60
  text "0,400mm (15,75mil)" at 9238.2,-5049.07 h60
  text "PTH" at 10583.8,-5049.07 h60
  text "Round" at 11089.68,-5049.07 h60
  text "11. PCB manufacturer may use tear drops to improve annular rings as long as DRC rules are followed" at -1421.47,-5167.93 h100
  text "262" at 8540.38,-5199.07 h60
  text "0,300mm (11,81mil)" at 9238.2,-5199.07 h60
  text "PTH" at 10583.8,-5199.07 h60
  text "Round" at 11089.68,-5199.07 h60
  text "12. All via connections to power and ground planes are solid" at -1421.47,-5307.93 h100
  text "480 Total" at 8540.38,-5349.07 h60
  text "13. All unconnected pads on inner signal layers are removed" at -1421.47,-5447.93 h100
  text "14. All finished boards are to be 100% electrically tested" at -1421.46,-5587.93 h100
  text "15. Unless otherwise indicated, all linear toleracnes shall be XX.X +/-0.2mm and XX.XX +/- 0.1mm" at -1421.47,-5727.93 h100
  text "16. Gerber file GM1 shows board outline (milling line)" at -1421.48,-5867.94 h100
  text "17. Table 1 shows Layer stack details" at -1421.49,-6007.96 h100
  text "Additional notes:" at -1416.47,-6272.93 h130
  text "A1. Finished board thickness = 1.6mm +/- 10%; measured over top/bottom copper and solder mask" at -1416.46,-6412.93 h100

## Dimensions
0,2362.2 to 4133.86,2362.2 on Dimensions
78.74,2440.94 to 78.74,0 on Dimensions
145,2295 to 3990,2295 on MechTop
145,2295 to 145,145 on MechTop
